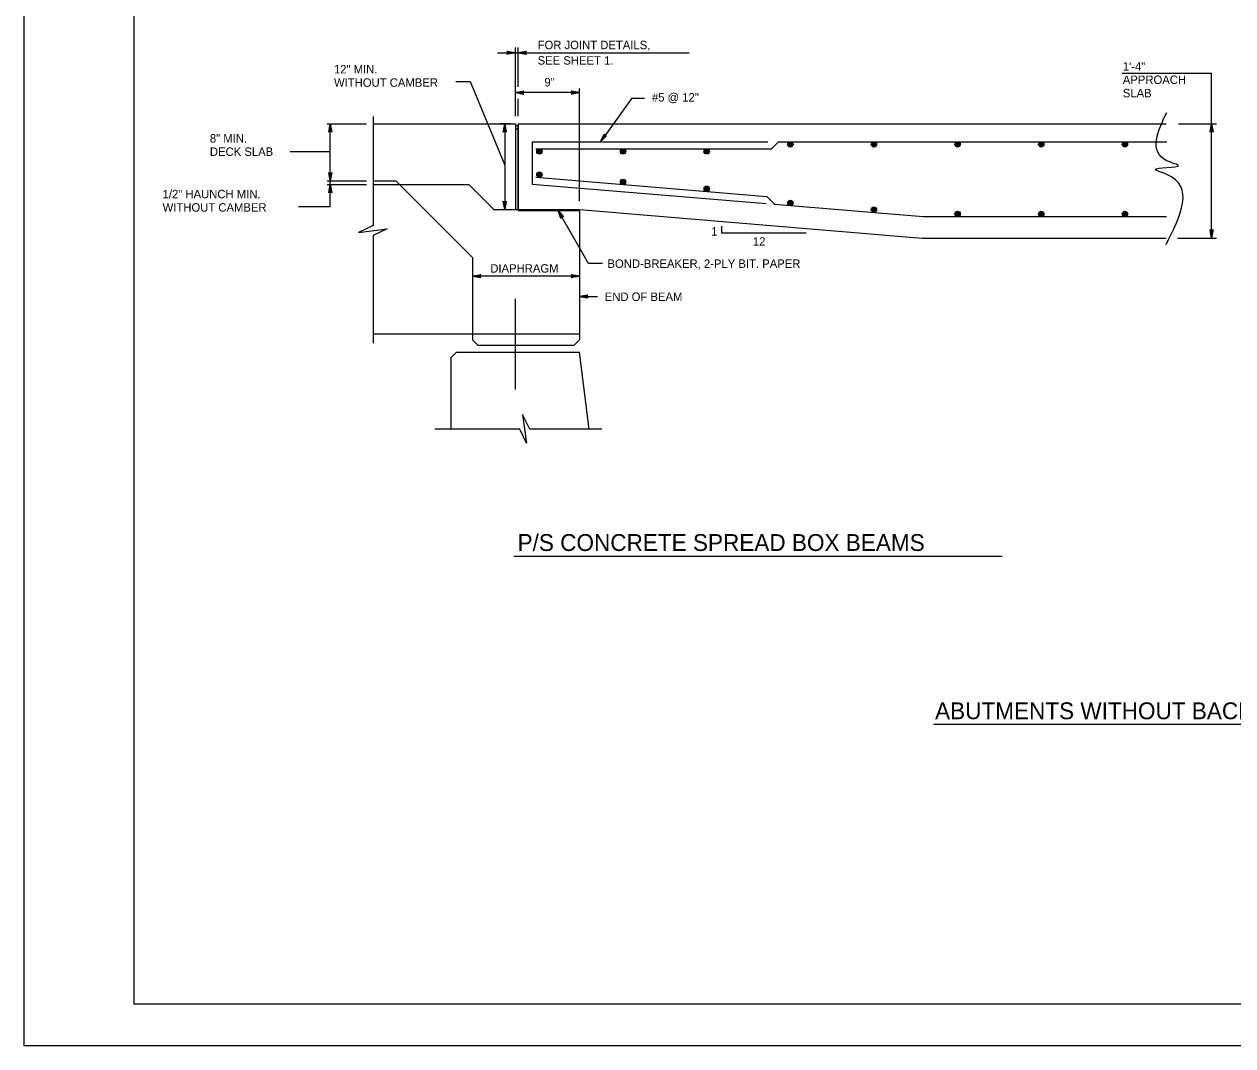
# Model space of a CAD drawing. Extents: x 638079 to 640019, y 297691 to 298879.
# Drawn here: x 638274 to 638704.2, y 297691.2 to 298055 of the extents above; entities that cross this region are included whole.
import ezdxf

# ---------------------------------------------------------------- set-up
doc = ezdxf.new("R2010")
doc.units = 0
doc.layers.add('1', color=7, linetype='Continuous')
doc.layers.add('PLT-BNDY', color=7, linetype='Continuous')

msp = doc.modelspace()

# ---------------------------------------------------------------- linework, layer by layer
at = {"layer": '1'}
for p, q in [((638448.85, 298022.28), (638448.85, 298046.71)), ((638449.8, 298032.67), (638449.8, 298046.71)), ((638442.52, 298044.85), (638510.73, 298044.85)), ((638664.75, 298037.58), (638696.63, 298037.58)), ((638696.63, 297978.86), (638696.63, 298037.58)), ((638471.71, 298030.62), (638448.85, 298030.62)), ((638471.71, 297991.94), (638471.71, 298032.13)), ((638449.8, 298022.28), (638449.8, 298028.47)), ((638490.27, 298028.61), (638479.1, 298013.15)), ((638490.27, 298028.61), (638494.8, 298028.61)), ((638398.25, 298022.13), (638398.25, 297983.32)), ((638381.86, 298019.5), (638395.92, 298019.5)), ((638382.98, 297990.08), (638382.98, 298019.5)), ((638398.25, 298019.5), (638448.85, 298019.5)), ((638447.1, 298019.5), (638443.31, 298019.5)), ((638445.06, 298019.5), (638445.06, 297989.02)), ((638448.85, 298019.5), (638448.85, 297989.02)), ((638448.85, 298017.59), (638449.8, 298017.59)), ((638449.8, 298019.5), (638680.46, 298019.5)), ((638449.8, 298019.5), (638449.8, 297989.02)), ((638684.79, 298019.5), (638698.38, 298019.5)), ((638454.88, 298013.15), (638454.88, 297998.07)), ((638454.88, 298013.15), (638538.7, 298013.15)), ((638539.97, 298010.61), (638542.51, 298013.15)), ((638542.51, 298013.15), (638680.64, 298013.15)), ((638368.73, 298009.65), (638382.98, 298009.65)), ((638456.1, 298010.61), (638539.97, 298010.61)), ((638456.1, 298000.51), (638538.33, 297993.66)), ((638381.86, 297999.18), (638395.92, 297999.18)), ((638381.86, 297997.91), (638395.92, 297997.91)), ((638398.25, 297999.18), (638406.35, 297999.18)), ((638398.25, 297997.91), (638407.63, 297997.91)), ((638433.61, 297971.93), (638406.35, 297999.18)), ((638407.63, 297997.91), (638432.33, 297997.91)), ((638441.23, 297989.02), (638432.33, 297997.91)), ((638454.88, 297998.07), (638538.12, 297991.13)), ((638538.33, 297993.66), (638541.11, 297990.88)), ((638541.11, 297990.88), (638593.93, 297986.48)), ((638441.23, 297989.02), (638449.8, 297989.02)), ((638449.8, 297989.02), (638471.71, 297989.02)), ((638449.8, 297988.71), (638449.8, 297989.02)), ((638449.8, 297988.71), (638449.8, 297989.02)), ((638449.8, 297989.02), (638471.71, 297989.02)), ((638449.8, 297988.71), (638471.71, 297988.71)), ((638471.71, 297989.02), (638471.71, 297942.66)), ((638471.71, 297989.02), (638593.61, 297978.86)), ((638593.93, 297986.48), (638680.53, 297986.48)), ((638398.25, 297979.81), (638398.25, 297941.38)), ((638593.61, 297978.86), (638680.46, 297978.86)), ((638684.47, 297978.86), (638698.38, 297978.86)), ((638433.61, 297971.93), (638433.61, 297942.66)), ((638471.71, 297965.28), (638433.61, 297965.28)), ((638448.85, 297924.93), (638448.85, 297957.26)), ((638471.71, 297958.06), (638478.1, 297958.06)), ((638433.61, 297944.57), (638398.25, 297944.57)), ((638471.71, 297944.57), (638433.61, 297944.57)), ((638433.61, 297942.66), (638435.51, 297940.76)), ((638435.51, 297940.76), (638469.8, 297940.76)), ((638469.8, 297940.76), (638471.71, 297942.66)), ((638425.99, 297936.31), (638427.89, 297938.22)), ((638425.99, 297910.81), (638425.99, 297936.31)), ((638427.89, 297938.22), (638471.71, 297938.22)), ((638475.13, 297910.81), (638471.71, 297938.22)), ((638450.42, 297910.81), (638420.24, 297910.81)), ((638479.61, 297910.81), (638453.94, 297910.81)), ((638448.26, 297865.59), (638622.1, 297865.59)), ((638597.69, 297805.77), (638800.04, 297805.77)), ((638274.03, 297691.23), (638274.03, 297691.23))]:
    msp.add_line(p, q, dxfattribs=at)
for points in [[(639099.03, 297706.23), (639099.03, 298270.23), (638313.03, 298270.23), (638313.03, 297706.23), (639099.03, 297706.23), (639099.03, 297732.59), (638899.03, 297732.59), (638899.03, 297797.26), (639099.03, 297797.26), (639099.03, 297826.23), (638899.03, 297826.23), (638899.03, 297706.23), (638977.83, 297706.23), (638977.83, 297732.59), (638977.83, 297706.23), (639054.83, 297706.23), (639054.83, 297732.59), (639054.83, 297720.27), (639099.03, 297720.27)], [(638448.85, 298044.85), (638445.86, 298044.29), (638445.98, 298044.37), (638446.09, 298044.45), (638446.15, 298044.55), (638446.21, 298044.65), (638446.23, 298044.75), (638446.25, 298044.85), (638446.23, 298044.95), (638446.21, 298045.05), (638446.15, 298045.15), (638446.09, 298045.25), (638445.98, 298045.32), (638445.86, 298045.4), (638448.85, 298044.85), (638445.98, 298045.32), (638446.09, 298045.25), (638448.85, 298044.85), (638446.15, 298045.15), (638446.21, 298045.05), (638448.85, 298044.85), (638446.23, 298044.95), (638446.25, 298044.85), (638448.85, 298044.85), (638446.23, 298044.75), (638446.21, 298044.65), (638448.85, 298044.85), (638446.15, 298044.55), (638446.09, 298044.45), (638448.85, 298044.85), (638445.98, 298044.37)], [(638449.8, 298044.85), (638452.78, 298045.4), (638452.67, 298045.32), (638452.55, 298045.25), (638452.49, 298045.15), (638452.43, 298045.05), (638452.42, 298044.95), (638452.4, 298044.85), (638452.42, 298044.75), (638452.43, 298044.65), (638452.49, 298044.55), (638452.55, 298044.45), (638452.67, 298044.37), (638452.78, 298044.29), (638449.8, 298044.85), (638452.67, 298044.37), (638452.55, 298044.45), (638449.8, 298044.85), (638452.49, 298044.55), (638452.43, 298044.65), (638449.8, 298044.85), (638452.42, 298044.75), (638452.4, 298044.85), (638449.8, 298044.85), (638452.42, 298044.95), (638452.43, 298045.05), (638449.8, 298044.85), (638452.49, 298045.15), (638452.55, 298045.25), (638449.8, 298044.85), (638452.67, 298045.32)], [(638427.63, 298034.63), (638432.72, 298034.63), (638445.06, 298004.79)], [(638448.85, 298030.62), (638451.83, 298031.18), (638451.71, 298031.1), (638451.6, 298031.02), (638451.54, 298030.92), (638451.48, 298030.82), (638451.46, 298030.72), (638451.45, 298030.62), (638451.46, 298030.52), (638451.48, 298030.42), (638451.54, 298030.32), (638451.6, 298030.22), (638451.71, 298030.14), (638451.83, 298030.06), (638448.85, 298030.62), (638451.71, 298030.14), (638451.6, 298030.22), (638448.85, 298030.62), (638451.54, 298030.32), (638451.48, 298030.42), (638448.85, 298030.62), (638451.46, 298030.52), (638451.45, 298030.62), (638448.85, 298030.62), (638451.46, 298030.72), (638451.48, 298030.82), (638448.85, 298030.62), (638451.54, 298030.92), (638451.6, 298031.02), (638448.85, 298030.62), (638451.71, 298031.1)], [(638471.71, 298030.62), (638468.72, 298030.06), (638468.84, 298030.14), (638468.95, 298030.22), (638469.01, 298030.32), (638469.07, 298030.42), (638469.09, 298030.52), (638469.11, 298030.62), (638469.09, 298030.72), (638469.07, 298030.82), (638469.01, 298030.92), (638468.95, 298031.02), (638468.84, 298031.1), (638468.72, 298031.18), (638471.71, 298030.62), (638468.84, 298031.1), (638468.95, 298031.02), (638471.71, 298030.62), (638469.01, 298030.92), (638469.07, 298030.82), (638471.71, 298030.62), (638469.09, 298030.72), (638469.11, 298030.62), (638471.71, 298030.62), (638469.09, 298030.52), (638469.07, 298030.42), (638471.71, 298030.62), (638469.01, 298030.32), (638468.95, 298030.22), (638471.71, 298030.62), (638468.84, 298030.14)], [(638382.98, 298019.5), (638383.54, 298016.51), (638383.46, 298016.63), (638383.38, 298016.74), (638383.28, 298016.8), (638383.18, 298016.86), (638383.08, 298016.88), (638382.98, 298016.9), (638382.88, 298016.88), (638382.78, 298016.86), (638382.68, 298016.8), (638382.58, 298016.74), (638382.5, 298016.63), (638382.42, 298016.51), (638382.98, 298019.5), (638382.5, 298016.63), (638382.58, 298016.74), (638382.98, 298019.5), (638382.68, 298016.8), (638382.78, 298016.86), (638382.98, 298019.5), (638382.88, 298016.88), (638382.98, 298016.9), (638382.98, 298019.5), (638383.08, 298016.88), (638383.18, 298016.86), (638382.98, 298019.5), (638383.28, 298016.8), (638383.38, 298016.74), (638382.98, 298019.5), (638383.46, 298016.63)], [(638445.06, 298019.5), (638445.61, 298016.51), (638445.54, 298016.63), (638445.46, 298016.74), (638445.36, 298016.8), (638445.26, 298016.86), (638445.16, 298016.88), (638445.06, 298016.9), (638444.96, 298016.88), (638444.86, 298016.86), (638444.76, 298016.8), (638444.66, 298016.74), (638444.58, 298016.63), (638444.5, 298016.51), (638445.06, 298019.5), (638444.58, 298016.63), (638444.66, 298016.74), (638445.06, 298019.5), (638444.76, 298016.8), (638444.86, 298016.86), (638445.06, 298019.5), (638444.96, 298016.88), (638445.06, 298016.9), (638445.06, 298019.5), (638445.16, 298016.88), (638445.26, 298016.86), (638445.06, 298019.5), (638445.36, 298016.8), (638445.46, 298016.74), (638445.06, 298019.5), (638445.54, 298016.63)], [(638696.63, 298019.5), (638697.19, 298016.51), (638697.11, 298016.63), (638697.03, 298016.74), (638696.93, 298016.8), (638696.83, 298016.86), (638696.73, 298016.88), (638696.63, 298016.9), (638696.53, 298016.88), (638696.43, 298016.86), (638696.33, 298016.8), (638696.23, 298016.74), (638696.15, 298016.63), (638696.07, 298016.51), (638696.63, 298019.5), (638696.15, 298016.63), (638696.23, 298016.74), (638696.63, 298019.5), (638696.33, 298016.8), (638696.43, 298016.86), (638696.63, 298019.5), (638696.53, 298016.88), (638696.63, 298016.9), (638696.63, 298019.5), (638696.73, 298016.88), (638696.83, 298016.86), (638696.63, 298019.5), (638696.93, 298016.8), (638697.03, 298016.74), (638696.63, 298019.5), (638697.11, 298016.63)], [(638479.1, 298013.15), (638480.39, 298015.89), (638480.39, 298015.75), (638480.39, 298015.61), (638480.43, 298015.51), (638480.48, 298015.4), (638480.55, 298015.33), (638480.62, 298015.26), (638480.71, 298015.21), (638480.8, 298015.17), (638480.92, 298015.16), (638481.04, 298015.15), (638481.17, 298015.19), (638481.3, 298015.24), (638479.1, 298013.15), (638481.17, 298015.19), (638481.04, 298015.15), (638479.1, 298013.15), (638480.92, 298015.16), (638480.8, 298015.17), (638479.1, 298013.15), (638480.71, 298015.21), (638480.62, 298015.26), (638479.1, 298013.15), (638480.55, 298015.33), (638480.48, 298015.4), (638479.1, 298013.15), (638480.43, 298015.51), (638480.39, 298015.61), (638479.1, 298013.15), (638480.39, 298015.75)], [(638382.98, 297999.18), (638382.42, 298002.16), (638382.5, 298002.05), (638382.58, 298001.93), (638382.68, 298001.87), (638382.78, 298001.81), (638382.88, 298001.8), (638382.98, 298001.78), (638383.08, 298001.8), (638383.18, 298001.81), (638383.28, 298001.87), (638383.38, 298001.93), (638383.46, 298002.05), (638383.54, 298002.16), (638382.98, 297999.18), (638383.46, 298002.05), (638383.38, 298001.93), (638382.98, 297999.18), (638383.28, 298001.87), (638383.18, 298001.81), (638382.98, 297999.18), (638383.08, 298001.8), (638382.98, 298001.78), (638382.98, 297999.18), (638382.88, 298001.8), (638382.78, 298001.81), (638382.98, 297999.18), (638382.68, 298001.87), (638382.58, 298001.93), (638382.98, 297999.18), (638382.5, 298002.05)], [(638382.98, 297997.91), (638383.54, 297994.93), (638383.46, 297995.04), (638383.38, 297995.16), (638383.28, 297995.21), (638383.18, 297995.27), (638383.08, 297995.29), (638382.98, 297995.31), (638382.88, 297995.29), (638382.78, 297995.27), (638382.68, 297995.21), (638382.58, 297995.16), (638382.5, 297995.04), (638382.42, 297994.93), (638382.98, 297997.91), (638382.5, 297995.04), (638382.58, 297995.16), (638382.98, 297997.91), (638382.68, 297995.21), (638382.78, 297995.27), (638382.98, 297997.91), (638382.88, 297995.29), (638382.98, 297995.31), (638382.98, 297997.91), (638383.08, 297995.29), (638383.18, 297995.27), (638382.98, 297997.91), (638383.28, 297995.21), (638383.38, 297995.16), (638382.98, 297997.91), (638383.46, 297995.04)], [(638445.06, 297989.02), (638444.5, 297992), (638444.58, 297991.88), (638444.66, 297991.77), (638444.76, 297991.71), (638444.86, 297991.65), (638444.96, 297991.63), (638445.06, 297991.62), (638445.16, 297991.63), (638445.26, 297991.65), (638445.36, 297991.71), (638445.46, 297991.77), (638445.54, 297991.88), (638445.61, 297992), (638445.06, 297989.02), (638445.54, 297991.88), (638445.46, 297991.77), (638445.06, 297989.02), (638445.36, 297991.71), (638445.26, 297991.65), (638445.06, 297989.02), (638445.16, 297991.63), (638445.06, 297991.62), (638445.06, 297989.02), (638444.96, 297991.63), (638444.86, 297991.65), (638445.06, 297989.02), (638444.76, 297991.71), (638444.66, 297991.77), (638445.06, 297989.02), (638444.58, 297991.88)], [(638371.69, 297990.08), (638382.98, 297990.08)], [(638479.88, 297969.73), (638474.88, 297969.73), (638464.06, 297988.71)], [(638464.06, 297988.71), (638466.02, 297986.4), (638465.9, 297986.46), (638465.77, 297986.52), (638465.66, 297986.52), (638465.54, 297986.52), (638465.44, 297986.49), (638465.35, 297986.45), (638465.27, 297986.39), (638465.19, 297986.32), (638465.13, 297986.22), (638465.08, 297986.12), (638465.06, 297985.98), (638465.05, 297985.84), (638464.06, 297988.71), (638465.06, 297985.98), (638465.08, 297986.12), (638464.06, 297988.71), (638465.13, 297986.22), (638465.19, 297986.32), (638464.06, 297988.71), (638465.27, 297986.39), (638465.35, 297986.45), (638464.06, 297988.71), (638465.44, 297986.49), (638465.54, 297986.52), (638464.06, 297988.71), (638465.66, 297986.52), (638465.77, 297986.52), (638464.06, 297988.71), (638465.9, 297986.46)], [(638398.25, 297983.32), (638393.06, 297980.79), (638403.21, 297982.17), (638398.25, 297979.81)], [(638552.35, 297980.59), (638522.35, 297980.59), (638522.35, 297983.09)], [(638696.63, 297978.86), (638696.07, 297981.84), (638696.15, 297981.73), (638696.23, 297981.61), (638696.33, 297981.55), (638696.43, 297981.49), (638696.53, 297981.48), (638696.63, 297981.46), (638696.73, 297981.48), (638696.83, 297981.49), (638696.93, 297981.55), (638697.03, 297981.61), (638697.11, 297981.73), (638697.19, 297981.84), (638696.63, 297978.86), (638697.11, 297981.73), (638697.03, 297981.61), (638696.63, 297978.86), (638696.93, 297981.55), (638696.83, 297981.49), (638696.63, 297978.86), (638696.73, 297981.48), (638696.63, 297981.46), (638696.63, 297978.86), (638696.53, 297981.48), (638696.43, 297981.49), (638696.63, 297978.86), (638696.33, 297981.55), (638696.23, 297981.61), (638696.63, 297978.86), (638696.15, 297981.73)], [(638433.61, 297965.28), (638436.59, 297965.84), (638436.47, 297965.76), (638436.36, 297965.68), (638436.3, 297965.58), (638436.24, 297965.48), (638436.22, 297965.38), (638436.21, 297965.28), (638436.22, 297965.18), (638436.24, 297965.08), (638436.3, 297964.98), (638436.36, 297964.88), (638436.47, 297964.8), (638436.59, 297964.72), (638433.61, 297965.28), (638436.47, 297964.8), (638436.36, 297964.88), (638433.61, 297965.28), (638436.3, 297964.98), (638436.24, 297965.08), (638433.61, 297965.28), (638436.22, 297965.18), (638436.21, 297965.28), (638433.61, 297965.28), (638436.22, 297965.38), (638436.24, 297965.48), (638433.61, 297965.28), (638436.3, 297965.58), (638436.36, 297965.68), (638433.61, 297965.28), (638436.47, 297965.76)], [(638471.71, 297965.28), (638468.72, 297964.72), (638468.84, 297964.8), (638468.95, 297964.88), (638469.01, 297964.98), (638469.07, 297965.08), (638469.09, 297965.18), (638469.11, 297965.28), (638469.09, 297965.38), (638469.07, 297965.48), (638469.01, 297965.58), (638468.95, 297965.68), (638468.84, 297965.76), (638468.72, 297965.84), (638471.71, 297965.28), (638468.84, 297965.76), (638468.95, 297965.68), (638471.71, 297965.28), (638469.01, 297965.58), (638469.07, 297965.48), (638471.71, 297965.28), (638469.09, 297965.38), (638469.11, 297965.28), (638471.71, 297965.28), (638469.09, 297965.18), (638469.07, 297965.08), (638471.71, 297965.28), (638469.01, 297964.98), (638468.95, 297964.88), (638471.71, 297965.28), (638468.84, 297964.8)], [(638471.71, 297958.06), (638474.69, 297958.62), (638474.57, 297958.54), (638474.46, 297958.46), (638474.4, 297958.36), (638474.34, 297958.26), (638474.32, 297958.16), (638474.31, 297958.06), (638474.32, 297957.96), (638474.34, 297957.86), (638474.4, 297957.76), (638474.46, 297957.66), (638474.57, 297957.58), (638474.69, 297957.5), (638471.71, 297958.06), (638474.57, 297957.58), (638474.46, 297957.66), (638471.71, 297958.06), (638474.4, 297957.76), (638474.34, 297957.86), (638471.71, 297958.06), (638474.32, 297957.96), (638474.31, 297958.06), (638471.71, 297958.06), (638474.32, 297958.16), (638474.34, 297958.26), (638471.71, 297958.06), (638474.4, 297958.36), (638474.46, 297958.46), (638471.71, 297958.06), (638474.57, 297958.54)], [(638453.94, 297910.81), (638451.4, 297916), (638452.78, 297905.85), (638450.42, 297910.81)]]:
    msp.add_lwpolyline(points, dxfattribs=at)
for points in [[(638448.85, 298017.59), (638449.8, 298017.59), (638449.8, 298018.86), (638448.85, 298018.86)], [(638448.85, 297989.02), (638449.8, 297989.02), (638449.8, 298017.59), (638448.85, 298017.59)]]:
    msp.add_lwpolyline(points, close=True, dxfattribs=at)
for centre, radius in [((638546.71, 298012.2), 0.952), ((638546.71, 298012.2), 0.714), ((638546.71, 298012.2), 0.476), ((638546.71, 298012.2), 0.238), ((638576.47, 298012.2), 0.952), ((638576.47, 298012.2), 0.714), ((638576.47, 298012.2), 0.476), ((638576.47, 298012.2), 0.238), ((638606.24, 298012.2), 0.952), ((638606.24, 298012.2), 0.714), ((638606.24, 298012.2), 0.476), ((638606.24, 298012.2), 0.238), ((638636, 298012.2), 0.952), ((638636, 298012.2), 0.714), ((638636, 298012.2), 0.476), ((638636, 298012.2), 0.238), ((638665.77, 298012.2), 0.952), ((638665.77, 298012.2), 0.714), ((638665.77, 298012.2), 0.476), ((638665.77, 298012.2), 0.238), ((638457.42, 298009.66), 0.952), ((638457.42, 298009.66), 0.714), ((638457.42, 298009.66), 0.476), ((638457.42, 298009.66), 0.238), ((638487.18, 298009.66), 0.952), ((638487.18, 298009.66), 0.714), ((638487.18, 298009.66), 0.476), ((638487.18, 298009.66), 0.238), ((638516.95, 298009.66), 0.952), ((638516.95, 298009.66), 0.714), ((638516.95, 298009.66), 0.476), ((638516.95, 298009.66), 0.238), ((638457.42, 298001.4), 0.952), ((638457.42, 298001.4), 0.714), ((638457.42, 298001.4), 0.476), ((638457.42, 298001.4), 0.238), ((638487.18, 297998.88), 0.952), ((638487.18, 297998.88), 0.714), ((638487.18, 297998.88), 0.476), ((638487.18, 297998.88), 0.238), ((638516.95, 297996.39), 0.952), ((638516.95, 297996.39), 0.714), ((638516.95, 297996.39), 0.476), ((638516.95, 297996.39), 0.238), ((638546.71, 297991.36), 0.952), ((638546.71, 297991.36), 0.714), ((638546.71, 297991.36), 0.476), ((638546.71, 297991.36), 0.238), ((638576.47, 297988.92), 0.952), ((638576.47, 297988.92), 0.714), ((638576.47, 297988.92), 0.476), ((638576.47, 297988.92), 0.238), ((638606.24, 297987.46), 0.952), ((638606.24, 297987.46), 0.714), ((638606.24, 297987.46), 0.476), ((638606.24, 297987.46), 0.238), ((638636, 297987.45), 0.952), ((638636, 297987.45), 0.714), ((638636, 297987.45), 0.476), ((638636, 297987.45), 0.238), ((638665.77, 297987.43), 0.952), ((638665.77, 297987.43), 0.714), ((638665.77, 297987.43), 0.476), ((638665.77, 297987.43), 0.238)]:
    msp.add_circle(centre, radius, dxfattribs=at)
msp.add_spline([(638680.46, 297976.6), (638680.67, 298001.53), (638676.51, 298003.31), (638684.84, 298004.62), (638680.67, 298006.4), (638680.64, 298023.56)], degree=3, dxfattribs=at)
at = {"layer": 'PLT-BNDY'}
msp.add_lwpolyline([(638274.03, 298285.23), (639115.03, 298285.23), (639115.03, 297691.23), (638274.03, 297691.23)], close=True, dxfattribs=at)

# ---------------------------------------------------------------- texts
at = {"layer": '1'}
for s, height, p in [('FOR JOINT DETAILS,', 3, (638456.77, 298046.1)), ('SEE SHEET 1.', 3, (638456.77, 298040.6)), ('12" MIN.', 3, (638384.3, 298037.47)), ('1\'-4"', 3, (638665.03, 298038.45)), ('WITHOUT CAMBER', 3, (638384.3, 298032.72)), ('9"', 3, (638459.18, 298032.84)), ('APPROACH', 3, (638665.03, 298033.71)), ('#5 @ 12"', 3, (638497.47, 298027.45)), ('SLAB', 3, (638665.03, 298028.96)), ('8" MIN.', 3, (638340.13, 298012.85)), ('DECK SLAB', 3, (638340.13, 298008.11)), ('1/2" HAUNCH MIN.', 3, (638323.31, 297993.01)), ('WITHOUT CAMBER', 3, (638323.31, 297988.26)), ('1', 3, (638518.54, 297979.74)), ('12', 3, (638533.36, 297976.13)), ('DIAPHRAGM', 3, (638439.92, 297966.54)), ('BOND-BREAKER, 2-PLY BIT. PAPER', 3, (638481.63, 297968.24)), ('END OF BEAM', 3, (638480.66, 297956.45)), ('P/S CONCRETE SPREAD BOX BEAMS', 6, (638449.63, 297867.43)), ('ABUTMENTS WITHOUT BACKWALL DETAILS', 6, (638598.22, 297807.52))]:
    msp.add_text(s, height=height, dxfattribs=at).set_placement(p)

doc.saveas('drawing.dxf')
